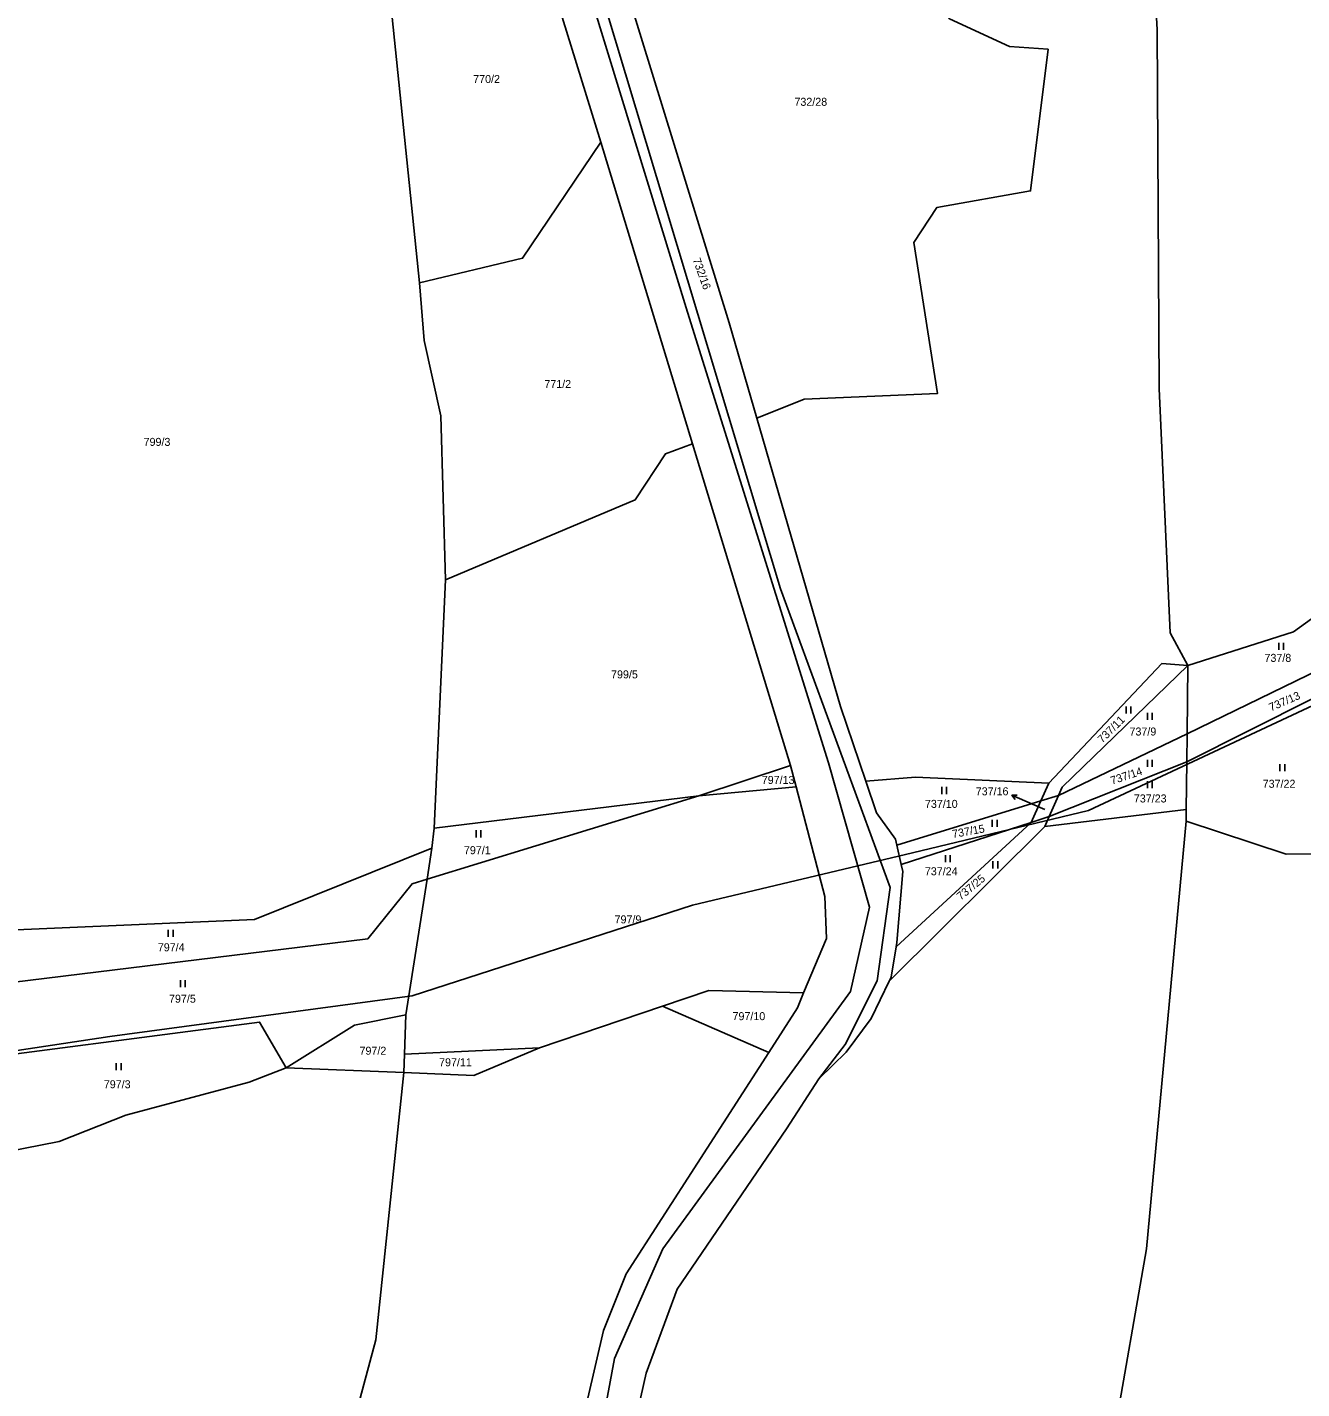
# Model space of a CAD drawing. Extents: x -588699 to -585793, y -1060280 to -1056731.
# Drawn here: x -587400.4 to -587129.7, y -1058097.1 to -1057807.9 of the extents above; entities that cross this region are included whole.
import ezdxf

# ---------------------------------------------------------------- set-up
doc = ezdxf.new("R2010")
doc.units = 0
for name, color, linetype in [('Druh pozemku', 7, 'Continuous'), ('Parcela nároku', 7, 'Continuous'), ('Parcelní číslo', 7, 'Continuous'), ('Silnice', 7, 'Continuous'), ('Vnější obvod_k šeření', 7, 'Continuous')]:
    doc.layers.add(name, color=color, linetype=linetype)

msp = doc.modelspace()

# ---------------------------------------------------------------- linework, layer by layer
at = {"layer": 'Druh pozemku'}
for p, q in [((-587134.62, -1057938.63), (-587134.62, -1057940.13)), ((-587133.59, -1057940.13), (-587133.59, -1057938.63)), ((-587167.05, -1057952.14), (-587167.05, -1057953.64)), ((-587166.03, -1057953.64), (-587166.03, -1057952.14)), ((-587162.49, -1057953.53), (-587162.49, -1057955.03)), ((-587161.46, -1057955.03), (-587161.46, -1057953.53)), ((-587162.49, -1057963.49), (-587162.49, -1057964.99)), ((-587161.46, -1057964.99), (-587161.46, -1057963.49)), ((-587134.36, -1057964.4), (-587134.36, -1057965.9)), ((-587133.33, -1057965.9), (-587133.33, -1057964.4)), ((-587206.17, -1057969.26), (-587206.17, -1057970.76)), ((-587205.15, -1057970.76), (-587205.15, -1057969.26)), ((-587162.49, -1057968.04), (-587162.49, -1057969.54)), ((-587161.46, -1057969.54), (-587161.46, -1057968.04)), ((-587195.48, -1057976.22), (-587195.48, -1057977.72)), ((-587194.45, -1057977.72), (-587194.45, -1057976.22)), ((-587305.09, -1057978.46), (-587305.09, -1057979.96)), ((-587304.07, -1057979.96), (-587304.07, -1057978.46)), ((-587205.41, -1057983.73), (-587205.41, -1057985.23)), ((-587204.39, -1057985.23), (-587204.39, -1057983.73)), ((-587195.33, -1057985.05), (-587195.33, -1057986.55)), ((-587194.31, -1057986.55), (-587194.31, -1057985.05)), ((-587370.48, -1057999.59), (-587370.48, -1058001.09)), ((-587369.45, -1058001.09), (-587369.45, -1057999.59)), ((-587367.89, -1058010.27), (-587367.89, -1058011.77)), ((-587366.86, -1058011.77), (-587366.86, -1058010.27)), ((-587381.54, -1058027.92), (-587381.54, -1058029.42)), ((-587380.52, -1058029.42), (-587380.52, -1058027.92))]:
    msp.add_line(p, q, dxfattribs=at)
at = {"layer": 'Parcela nároku'}
for points in [[(-587105.26, -1057680.3), (-587092.55, -1057679.16), (-587091.45, -1057679.28), (-587089.66, -1057788.78), (-587094.44, -1057823.73), (-587106.88, -1057856.27), (-587110.11, -1057920.88), (-587131.45, -1057936.32), (-587153.9, -1057943.43), (-587157.66, -1057936.51), (-587160.04, -1057884.63), (-587160.43, -1057808.36), (-587163.92, -1057746.79), (-587163.78, -1057671.48), (-587135.86, -1057679.58)], [(-587201.39, -1057716.13), (-587196.9, -1057745.45), (-587205.31, -1057747.4), (-587227.59, -1057770.48), (-587204.53, -1057806.07), (-587191.82, -1057811.94), (-587183.61, -1057812.52), (-587187.33, -1057842.64), (-587207.26, -1057846.16), (-587212.15, -1057853.59), (-587207.07, -1057885.66), (-587235.41, -1057886.84), (-587245.5, -1057890.9), (-587251.37, -1057870.69), (-587279.35, -1057779.69), (-587233.35, -1057766.22)], [(-587292.97, -1057752.59), (-587289.22, -1057747.59), (-587279.35, -1057779.69), (-587251.37, -1057870.69), (-587245.5, -1057890.9), (-587227.72, -1057952.13), (-587222.32, -1057968), (-587220.02, -1057974.76), (-587215.98, -1057980.34), (-587215.7, -1057981.62), (-587214.8, -1057985.72), (-587214.47, -1057987.23), (-587215.75, -1058002.3), (-587215.9, -1058003.21), (-587216.96, -1058009.69), (-587217.36, -1058010.52), (-587221.2, -1058018.45), (-587226.47, -1058025.59), (-587232.29, -1058031.28), (-587226.68, -1058023.99), (-587219.92, -1058010.46), (-587217.15, -1057990.59), (-587240.42, -1057927.14), (-587284.37, -1057781.22)], [(-587312.47, -1057772.97), (-587300.2, -1057762.4), (-587278.63, -1057832.29), (-587295.22, -1057856.94), (-587317.1, -1057862.19), (-587325.59, -1057779.62)], [(-587312.56, -1057890.39), (-587316.12, -1057874.39), (-587317.1, -1057862.19), (-587325.59, -1057779.62), (-587335.22, -1057784.42), (-587343.85, -1057787.3), (-587346.29, -1057788.14), (-587408.57, -1057807.33), (-587415.87, -1057861.66), (-587420.43, -1057913.52), (-587426.26, -1057940.15), (-587440.47, -1058001.25), (-587352.15, -1057997.44), (-587314.47, -1057982.24), (-587313.99, -1057978.03), (-587311.62, -1057925.29)], [(-587295.22, -1057856.94), (-587278.63, -1057832.29), (-587259.11, -1057896.38), (-587264.84, -1057898.46), (-587271.3, -1057908.25), (-587311.62, -1057925.29), (-587312.56, -1057890.39), (-587316.12, -1057874.39), (-587317.1, -1057862.19)], [(-587264.84, -1057898.46), (-587259.11, -1057896.38), (-587238.3, -1057964.73), (-587257.77, -1057971.13), (-587313.99, -1057978.03), (-587311.62, -1057925.29), (-587271.3, -1057908.25)], [(-587154.07, -1057957.94), (-587153.9, -1057943.43), (-587131.45, -1057936.32), (-587110.11, -1057920.88), (-587113.02, -1057938.03)], [(-587113.02, -1057938.03), (-587154.07, -1057957.94), (-587154.14, -1057963.9), (-587113.98, -1057943.72)], [(-587159.44, -1057943.06), (-587153.9, -1057943.43), (-587180.6, -1057969.28), (-587181.38, -1057971.06), (-587185.13, -1057972.21), (-587183.46, -1057968.48)], [(-587180.6, -1057969.28), (-587153.9, -1057943.43), (-587154.07, -1057957.94), (-587181.38, -1057971.06)], [(-587113.33, -1057983.29), (-587117.94, -1057967.14), (-587113.98, -1057943.72), (-587154.14, -1057963.9), (-587154.26, -1057974.05), (-587154.26, -1057976.54), (-587133.01, -1057983.57)], [(-587183.36, -1057975.55), (-587181.38, -1057971.06), (-587154.07, -1057957.94), (-587154.14, -1057963.9)], [(-587238.3, -1057964.73), (-587257.77, -1057971.13), (-587237.13, -1057969.21)], [(-587184.29, -1057977.65), (-587183.36, -1057975.55), (-587154.14, -1057963.9), (-587154.26, -1057974.05)], [(-587222.32, -1057968), (-587211.73, -1057967.19), (-587183.46, -1057968.48), (-587185.13, -1057972.21), (-587215.7, -1057981.62), (-587215.98, -1057980.34), (-587220.02, -1057974.76)], [(-587257.77, -1057971.13), (-587237.13, -1057969.21), (-587231.03, -1057992.55), (-587230.7, -1058001.44), (-587235.53, -1058012.99), (-587255.65, -1058012.51), (-587265.47, -1058015.84), (-587291.65, -1058024.66), (-587320.33, -1058026.05), (-587320.02, -1058017.68), (-587315.51, -1057988.87)], [(-587313.99, -1057978.03), (-587257.77, -1057971.13), (-587315.51, -1057988.87), (-587314.47, -1057982.24)], [(-587185.13, -1057972.21), (-587215.7, -1057981.62), (-587214.8, -1057985.72), (-587187.17, -1057976.78)], [(-587185.13, -1057972.21), (-587181.38, -1057971.06), (-587183.36, -1057975.55), (-587187.17, -1057976.78)], [(-587282.69, -1058201.62), (-587280.14, -1058143.43), (-587268.98, -1058093.77), (-587262.36, -1058075.98), (-587239.18, -1058041.88), (-587232.29, -1058031.28), (-587226.47, -1058025.59), (-587221.2, -1058018.45), (-587217.36, -1058010.52), (-587184.29, -1057977.65), (-587154.26, -1057974.05), (-587154.26, -1057976.54), (-587162.67, -1058067.38), (-587169.7, -1058107.61), (-587172.24, -1058142), (-587191.01, -1058241.74), (-587222.83, -1058325.23), (-587257.35, -1058309.41), (-587259.55, -1058300.98), (-587264.68, -1058293.6), (-587272.84, -1058298.75), (-587274.29, -1058301.65), (-587295.9, -1058291.75)], [(-587216.96, -1058009.69), (-587215.9, -1058003.21), (-587187.17, -1057976.78), (-587183.36, -1057975.55), (-587184.29, -1057977.65), (-587217.36, -1058010.52)], [(-587093.47, -1058042.85), (-587083.2, -1058085.63), (-587087.45, -1058131.23), (-587096.95, -1058176.54), (-587108.49, -1058212.36), (-587125.77, -1058278.15), (-587153.1, -1058357.53), (-587158, -1058368.22), (-587193.45, -1058428.69), (-587200.12, -1058424.25), (-587247.18, -1058391.8), (-587222.83, -1058325.23), (-587191.01, -1058241.74), (-587172.24, -1058142), (-587169.7, -1058107.61), (-587162.67, -1058067.38), (-587154.26, -1057976.54), (-587133.01, -1057983.57), (-587113.33, -1057983.29)], [(-587215.9, -1058003.21), (-587215.75, -1058002.3), (-587214.47, -1057987.23), (-587214.8, -1057985.72), (-587187.17, -1057976.78)], [(-587440.47, -1058001.25), (-587352.15, -1057997.44), (-587314.47, -1057982.24), (-587315.51, -1057988.87), (-587318.68, -1057989.84), (-587328.06, -1058001.49), (-587439.66, -1058015.2)], [(-587318.68, -1057989.84), (-587328.06, -1058001.49), (-587439.66, -1058015.2), (-587439.24, -1058022.46), (-587442.28, -1058040.11), (-587427.58, -1058039.43), (-587422.89, -1058028.6), (-587351.1, -1058019.22), (-587345.44, -1058028.92), (-587330.9, -1058019.86), (-587320.02, -1058017.68), (-587315.51, -1057988.87)], [(-587255.65, -1058012.51), (-587235.53, -1058012.99), (-587236.85, -1058016.16), (-587242.92, -1058025.69), (-587265.47, -1058015.84)], [(-587351.4, -1058206.3), (-587339.42, -1058135.2), (-587326.37, -1058086.73), (-587320.47, -1058029.95), (-587305.56, -1058030.56), (-587291.65, -1058024.66), (-587265.47, -1058015.84), (-587242.92, -1058025.69), (-587273.24, -1058072.71), (-587278.03, -1058084.71), (-587291.55, -1058143.14), (-587293.59, -1058158.32), (-587293.6, -1058172.06), (-587295.78, -1058175.26), (-587295.94, -1058190.13), (-587293.6, -1058194.6), (-587293.61, -1058198.3), (-587298.84, -1058246.13), (-587305.16, -1058294.29), (-587309.56, -1058312.62), (-587312.09, -1058322.87), (-587377.92, -1058277.75)], [(-587444.9, -1058047.44), (-587442.28, -1058040.11), (-587427.58, -1058039.43), (-587422.89, -1058028.6), (-587351.1, -1058019.22), (-587345.44, -1058028.92), (-587353.28, -1058031.95), (-587379.52, -1058038.97), (-587393.66, -1058044.61), (-587445.31, -1058054.69), (-587456.91, -1058059.97)], [(-587345.44, -1058028.92), (-587330.9, -1058019.86), (-587320.02, -1058017.68), (-587320.33, -1058026.05), (-587320.47, -1058029.95)], [(-587320.47, -1058029.95), (-587320.33, -1058026.05), (-587291.65, -1058024.66), (-587305.56, -1058030.56)], [(-587345.44, -1058028.92), (-587320.47, -1058029.95), (-587326.37, -1058086.73), (-587339.42, -1058135.2), (-587351.4, -1058206.3), (-587377.92, -1058277.75), (-587409.09, -1058258.83), (-587438.17, -1058230.02), (-587444.54, -1058218.88), (-587478.83, -1058188.89), (-587488.81, -1058140.74), (-587488.94, -1058128.88), (-587485.87, -1058116.62), (-587469.24, -1058080.38), (-587460.27, -1058069.38), (-587445.31, -1058054.69), (-587393.66, -1058044.61), (-587379.52, -1058038.97), (-587353.28, -1058031.95)]]:
    msp.add_lwpolyline(points, close=True, dxfattribs=at)
for points in [[(-587163.92, -1057746.79), (-587160.43, -1057808.36), (-587160.04, -1057884.63), (-587157.66, -1057936.51), (-587153.9, -1057943.43), (-587159.44, -1057943.06), (-587183.46, -1057968.48), (-587211.73, -1057967.19), (-587222.32, -1057968), (-587227.72, -1057952.13), (-587245.5, -1057890.9), (-587235.41, -1057886.84), (-587207.07, -1057885.66), (-587212.15, -1057853.59), (-587207.26, -1057846.16), (-587187.33, -1057842.64), (-587183.61, -1057812.52), (-587191.82, -1057811.94), (-587204.53, -1057806.07)], [(-587300.2, -1057762.4), (-587278.63, -1057832.29), (-587259.11, -1057896.38), (-587238.3, -1057964.73), (-587237.13, -1057969.21), (-587231.03, -1057992.55), (-587230.7, -1058001.44), (-587235.53, -1058012.99), (-587236.85, -1058016.16), (-587242.92, -1058025.69), (-587273.24, -1058072.71), (-587278.03, -1058084.71), (-587291.55, -1058143.14)], [(-587280.14, -1058143.43), (-587268.98, -1058093.77), (-587262.36, -1058075.98), (-587239.18, -1058041.88), (-587232.29, -1058031.28), (-587226.68, -1058023.99), (-587219.92, -1058010.46), (-587217.15, -1057990.59), (-587240.42, -1057927.14), (-587284.37, -1057781.22)]]:
    msp.add_lwpolyline(points, dxfattribs=at)
at = {"layer": 'Parcelní číslo'}
for p, q in [((-587188.55, -1057972.22), (-587191.3, -1057971.03)), ((-587184.32, -1057974.04), (-587188.55, -1057972.22))]:
    msp.add_line(p, q, dxfattribs=at)
msp.add_lwpolyline([(-587190.58, -1057971.89), (-587191.3, -1057971.03), (-587190.19, -1057970.97)], dxfattribs=at)
at = {"layer": 'Silnice'}
msp.add_lwpolyline([(-587345.08, -1058454.6), (-587343.22, -1058435.34), (-587340.2, -1058422.73), (-587333.83, -1058405.7), (-587323.03, -1058372.85), (-587310.8, -1058335.66), (-587304.81, -1058309.03), (-587295.59, -1058255.42), (-587289.86, -1058202.05), (-587287.36, -1058153.18), (-587282.38, -1058126.49), (-587275.7, -1058090.71), (-587265.43, -1058067.39), (-587238.5, -1058030.49), (-587225.54, -1058012.73), (-587221.55, -1057994.83), (-587230.27, -1057964.15), (-587260.19, -1057868.4), (-587294.78, -1057755.78)], dxfattribs=at)
at = {"layer": 'Vnější obvod_k šeření'}
msp.add_lwpolyline([(-587598.78, -1058147.31), (-587587.54, -1058137.18), (-587578.39, -1058122.34), (-587562.78, -1058087.91), (-587557.09, -1058081.9), (-587547.48, -1058078.1), (-587531.42, -1058078.42), (-587519.59, -1058074.95), (-587509.13, -1058065.73), (-587501.68, -1058061.09), (-587491.48, -1058057.56), (-587477.36, -1058055.8), (-587461.22, -1058052.2), (-587453.76, -1058048.47), (-587450.1, -1058043.17), (-587447.95, -1058035.13), (-587445.79, -1058031.73), (-587382.9, -1058022.25), (-587318.71, -1058013.6), (-587259.11, -1057994.38), (-587212.43, -1057983.28), (-587175.02, -1057974.24), (-587119.54, -1057948.26)], dxfattribs=at)

# ---------------------------------------------------------------- texts
at = {"layer": 'Parcela nároku'}
for s, height, p in [('770/2', 1.7, (-587305.72, -1057819.71)), ('732/28', 1.7, (-587237.48, -1057824.55)), ('771/2', 1.7, (-587290.6, -1057884.5)), ('799/3', 1.7, (-587375.72, -1057896.8)), ('737/8', 1.7, (-587137.64, -1057942.68)), ('799/5', 1.7, (-587276.43, -1057946.19)), ('737/9', 1.7, (-587166.31, -1057958.33)), ('797/13', 1.7, (-587244.42, -1057968.62)), ('737/22', 1.7, (-587138.02, -1057969.43)), ('737/10', 1.7, (-587209.76, -1057973.7)), ('737/23', 1.7, (-587165.39, -1057972.55)), ('737/16', 0.1, (-587184.52, -1057974.04)), ('797/1', 1.7, (-587307.68, -1057983.54)), ('737/24', 1.7, (-587209.78, -1057988.02)), ('797/9', 1.7, (-587275.68, -1057998.24)), ('797/4', 1.7, (-587372.7, -1058004.17)), ('797/5', 1.7, (-587370.32, -1058015.09)), ('797/10', 1.7, (-587250.63, -1058018.8)), ('797/2', 1.7, (-587329.86, -1058026.14)), ('797/11', 1.7, (-587312.96, -1058028.6)), ('797/3', 1.7, (-587384.17, -1058033.27))]:
    msp.add_text(s, height=height, dxfattribs=at).set_placement(p)
for s, rotation, p in [('732/16', 289.8221, (-587259.12, -1057857.23)), ('737/13', 23.5271, (-587136.25, -1057953.22)), ('737/11', 45, (-587172.08, -1057960.06)), ('737/14', 18.435, (-587170.02, -1057968.79)), ('737/15', 10.112, (-587203.81, -1057980.11)), ('737/25', 39.4198, (-587202.15, -1057993.42))]:
    msp.add_text(s, height=1.7, rotation=rotation, dxfattribs=at).set_placement(p)
at = {"layer": 'Parcelní číslo'}
msp.add_text('737/16', height=1.7, dxfattribs=at).set_placement((-587198.97, -1057971.03))

doc.saveas('drawing.dxf')
